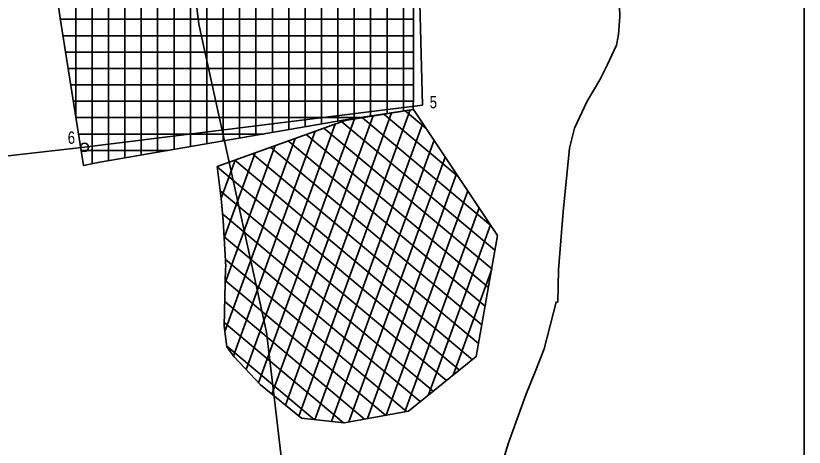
# Model space of a CAD drawing. Extents: x 308460 to 314812, y 245206 to 253414.
# Drawn here: x 312886 to 314812, y 246259 to 247312 of the extents above; entities that cross this region are included whole.
import ezdxf

# ---------------------------------------------------------------- set-up
doc = ezdxf.new("R2010")
doc.units = 0
doc.header["$LTSCALE"] = 11
for name, color, linetype, lineweight in [('1', 7, 'Continuous', 35), ('2', 7, 'Continuous', 35), ('44', 7, 'Continuous', 35), ('57', 7, 'Continuous', 13), ('63', 7, 'Continuous', 35), ('8', 7, 'Continuous', 35)]:
    doc.layers.add(name, color=color, linetype=linetype, lineweight=lineweight)

msp = doc.modelspace()

# ---------------------------------------------------------------- linework, layer by layer
at = {"layer": '1'}
for p, q in [((313072.72, 250815.85), (313072.72, 246950.8)), ((313112.72, 250812.1), (313112.72, 246958.32)), ((313152.72, 250804.95), (313152.72, 246965.21)), ((313032.72, 250802.91), (313032.72, 247066.95)), ((313192.72, 250797.56), (313192.72, 246972.09)), ((313232.72, 250791.28), (313232.72, 246978.97)), ((313272.72, 250790.21), (313272.72, 246985.85)), ((313312.72, 250790.43), (313312.72, 246992.73)), ((313352.72, 250791.66), (313352.72, 246999.61)), ((313392.72, 250780.57), (313392.72, 247006.49)), ((313432.72, 250757.04), (313432.72, 247013.38)), ((313472.72, 250731.15), (313472.72, 247020.26)), ((313512.72, 250707.22), (313512.72, 247027.14)), ((313552.72, 250695.66), (313552.72, 247034.02)), ((313592.72, 250332.33), (313592.72, 247040.9)), ((313632.72, 250319.08), (313632.72, 247047.78)), ((313672.72, 250305.82), (313672.72, 247054.67)), ((313712.72, 250292.56), (313712.72, 247061.18)), ((313752.72, 250279.3), (313752.72, 247067.41)), ((313792.72, 250266.05), (313792.72, 247073.64)), ((313832.72, 249379.2), (313832.72, 247079.87)), ((313857.18, 247303.3), (312995.27, 247303.3)), ((313857.24, 247263.3), (313001.61, 247263.3)), ((313857.3, 247223.3), (313007.95, 247223.3)), ((313857.36, 247183.3), (313014.28, 247183.3)), ((313857.41, 247143.3), (313020.62, 247143.3)), ((313857.04, 247103.3), (313026.96, 247103.3)), ((313726.32, 247063.3), (313033.3, 247063.3)), ((313490.41, 247023.3), (313039.64, 247023.3)), ((313257.91, 246983.3), (313045.98, 246983.3))]:
    msp.add_line(p, q, dxfattribs=at)
msp.add_lwpolyline([(313856.47, 247789.93), (313857.45, 247117.73), (313856.47, 247083.57), (313690.33, 247057.69), (313091.9, 246954.74), (313051.81, 246946.5), (312994.84, 247306.01), (312916.95, 247839.09)], dxfattribs=at)
msp.add_circle((313054, 246991), 10, dxfattribs=at)
at = {"layer": '2'}
for p, q in [((313544.47, 246361.83), (313803.97, 247074.79)), ((313577.3, 246335.07), (313849.23, 247082.18)), ((313967.42, 246918.65), (313785.03, 247071.69)), ((313888.42, 247037.16), (313837.12, 247080.21)), ((313479.15, 246416.27), (313713.45, 247060)), ((313511.65, 246388.59), (313758.71, 247067.39)), ((313616.6, 246326.08), (313880, 247049.78)), ((314056.41, 246739.55), (313682.4, 247053.38)), ((314046.42, 246800.15), (313732.95, 247063.18)), ((313417.86, 246481.77), (313617.43, 247030.1)), ((313448.46, 246448.88), (313666.39, 247047.64)), ((314048.41, 246694.05), (313638.79, 247037.75)), ((313396.86, 246541.04), (313568.48, 247012.55)), ((314040.4, 246648.55), (313595.19, 247022.12)), ((313397.59, 246659.99), (313519.53, 246995.01)), ((314032.4, 246603.05), (313551.59, 247006.5)), ((313657.59, 246321.77), (313907.54, 247008.48)), ((313395.2, 246770.37), (313470.58, 246977.46)), ((314016.39, 246512.05), (313464.38, 246975.24)), ((314024.39, 246557.55), (313507.98, 246990.87)), ((313387.86, 246867.15), (313421.62, 246959.92)), ((314001.3, 246472.5), (313420.77, 246959.61)), ((313699.8, 246320.79), (313935.07, 246967.18)), ((313969.48, 246446.98), (313378.6, 246942.79)), ((313745.4, 246329.1), (313962.6, 246925.88)), ((313937.66, 246421.46), (313385.72, 246884.59)), ((313790.99, 246337.41), (313990.14, 246884.57)), ((313836.58, 246345.72), (314017.67, 246843.27)), ((313905.84, 246395.95), (313391.47, 246827.55)), ((313893.96, 246386.42), (314045.21, 246801.97)), ((313874.02, 246370.43), (313395.09, 246772.3)), ((313840.41, 246346.42), (313398.18, 246717.49)), ((313954.07, 246434.63), (314048.33, 246693.59)), ((313789.29, 246337.1), (313397.72, 246665.66)), ((313738.16, 246327.78), (313396.61, 246614.38)), ((313686.75, 246318.71), (313395.5, 246563.09)), ((313615.6, 246326.18), (313401, 246506.26))]:
    msp.add_line(p, q, dxfattribs=at)
msp.add_lwpolyline([(313378.4, 246944.43), (313690.32, 247056.22), (313857.5, 247083.54), (314062.76, 246775.63), (314010.76, 246480.09), (313845.15, 246347.28), (313687.77, 246318.6), (313584.15, 246329.49), (313483.97, 246411.15), (313419.33, 246479.82), (313401.31, 246503.65), (313395.31, 246554.15), (313398.36, 246695.69), (313399.21, 246699.05), (313392.83, 246812.49), (313388.02, 246865.84)], close=True, dxfattribs=at)
at = {"layer": '44'}
for points in [[(313270.28, 250415.53), (313264.26, 250334.41), (313262.92, 250311.23), (313262.48, 250311.15), (313262.48, 250311.15), (313233.08, 250153.27), (313214.37, 250007.23), (313203.68, 249931.53), (313180.29, 249879.95), (313179.64, 249878.53), (313198.35, 249881.07), (313169.05, 249261.72), (313181.38, 248931.71), (313161.76, 248653.16), (313223.2, 248110.39), (313279.96, 247727.01), (313333.63, 247291.48), (313498.65, 246539.99), (313521.29, 246346.59)], [(313521.29, 246346.59), (313612.16, 245570.07), (313700.21, 245206.03)]]:
    msp.add_lwpolyline(points, dxfattribs=at)
at = {"layer": '57', "lineweight": 35}
msp.add_lwpolyline([(314811.5, 253140.4), (312000.01, 253140.4), (312000.01, 245420.78), (314811.5, 245420.78)], close=True, dxfattribs=at)
at = {"layer": '63'}
msp.add_lwpolyline([(313174, 252254), (313681, 252228), (313651, 250798), (313806, 249892), (313879, 247094), (313054, 246991), (310687, 246723), (308500, 252995)], close=True, dxfattribs=at)
at = {"layer": '8'}
msp.add_lwpolyline([(314358.16, 247409.01), (314361.08, 247309.74), (314357.93, 247266.29), (314352.89, 247239.83), (314330.54, 247191.66), (314312.8, 247155.7), (314281.76, 247103.18), (314250.59, 247037.37), (314238.63, 246988.87), (314222.91, 246833.79), (314211.25, 246691.62), (314209.63, 246613.32), (314205.73, 246613.06), (314176.5, 246498.97), (314155.9, 246447.13), (314131.74, 246387.1), (314089.09, 246269.38), (314033.83, 246089.33)], dxfattribs=at)

# ---------------------------------------------------------------- texts
at = {"layer": '63', "width": 0.8}
for s, p in [('5', (313896.98, 247086.29)), ('6', (313013.11, 246999.49))]:
    msp.add_text(s, height=30, dxfattribs=at).set_placement(p)

doc.saveas('drawing.dxf')
